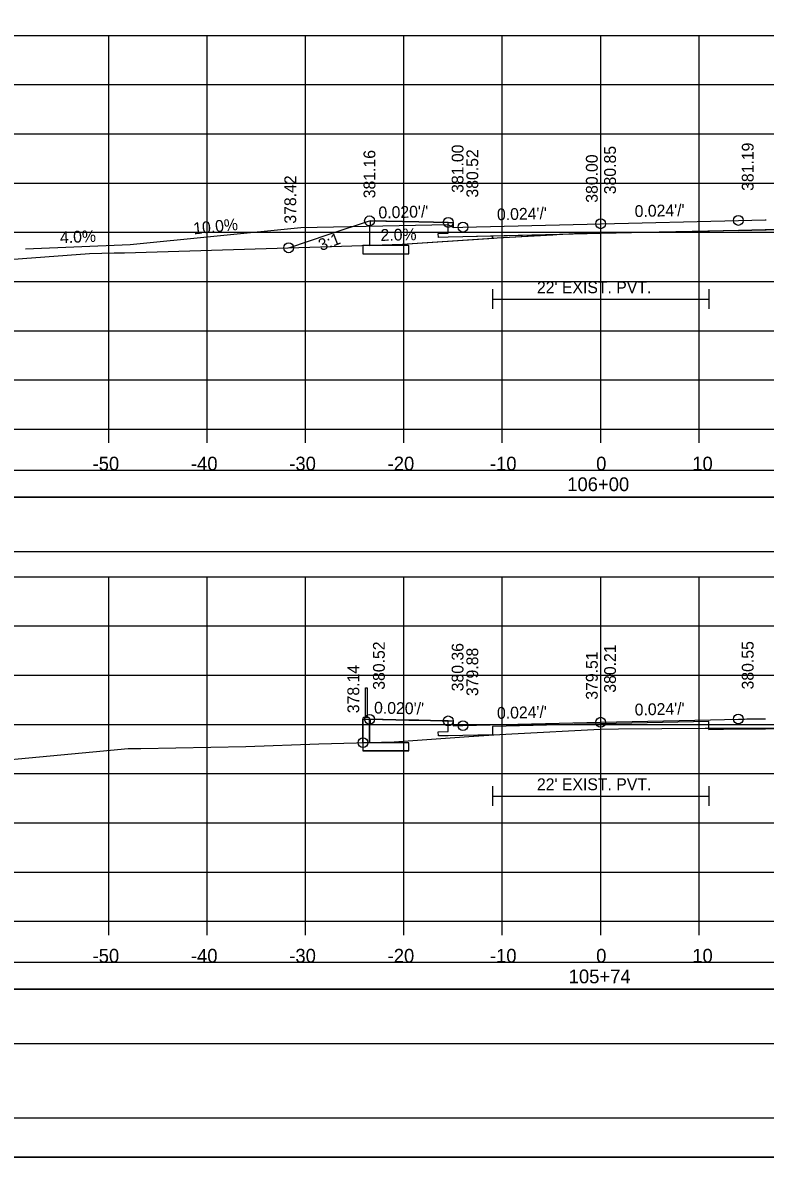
# Model space of a CAD drawing. Extents: x -37291014 to -37290680, y -936053 to -933067.
# Drawn here: x -37290901.9 to -37290826.4, y -934773.3 to -934658 of the extents above; entities that cross this region are included whole.
import ezdxf

# ---------------------------------------------------------------- set-up
doc = ezdxf.new("R2010")
doc.units = 0
for name, color, linetype in [('Default', 7, 'Continuous'), ('R_Alt Surface', 7, 'Continuous'), ('R_Axis', 7, 'Continuous'), ('R_Axis Annot', 7, 'Continuous'), ('R_Border', 7, 'Continuous'), ('R_Contours', 7, 'Continuous'), ('R_Drive', 7, 'Continuous'), ('R_Exist Surface', 7, 'Continuous'), ('R_Fin Surface', 7, 'Continuous'), ('R_Grid', 7, 'Continuous'), ('R_No Plot', 7, 'Continuous'), ('R_Water', 7, 'Continuous'), ('R_Xsect Elev', 7, 'Continuous'), ('R_Xsect Slope', 7, 'Continuous')]:
    doc.layers.add(name, color=color, linetype=linetype)

msp = doc.modelspace()

# ---------------------------------------------------------------- linework, layer by layer
at = {"layer": 'Default'}
for p, q in [((-37290867.02, -934728.59), (-37290867.02, -934725.59)), ((-37290867.02, -934725.59), (-37290866.85, -934725.59)), ((-37290866.85, -934725.59), (-37290866.85, -934728.59)), ((-37290867.21, -934728.61), (-37290867.27, -934728.67)), ((-37290866.67, -934728.59), (-37290867.21, -934728.59)), ((-37290867.21, -934728.59), (-37290867.21, -934728.61)), ((-37290866.67, -934728.61), (-37290867.21, -934728.61)), ((-37290866.67, -934728.61), (-37290866.67, -934728.59)), ((-37290866.6, -934728.67), (-37290866.67, -934728.61)), ((-37290867.27, -934728.67), (-37290867.27, -934731.99)), ((-37290866.6, -934731.16), (-37290866.6, -934728.67)), ((-37290862.6, -934731.99), (-37290867.27, -934731.99)), ((-37290862.6, -934731.16), (-37290866.6, -934731.16)), ((-37290862.6, -934731.99), (-37290862.6, -934731.16))]:
    msp.add_line(p, q, dxfattribs=at)
for points in [[(-37290992.31, -934706.2), (-37290693.89, -934706.2), (-37290693.89, -934703.5), (-37290992.31, -934703.5)], [(-37290992.31, -934711.72), (-37290693.89, -934711.72), (-37290693.89, -934706.2), (-37290992.31, -934706.2)], [(-37290992.31, -934756.2), (-37290693.89, -934756.2), (-37290693.89, -934753.5), (-37290992.31, -934753.5)], [(-37290992.31, -934761.72), (-37290693.89, -934761.72), (-37290693.89, -934756.2), (-37290992.31, -934756.2)]]:
    msp.add_lwpolyline(points, close=True, dxfattribs=at)
msp.add_lwpolyline([(-37290866.52, -934729.28), (-37290866.6, -934729.28), (-37290866.6, -934728.78), (-37290866.52, -934728.78), (-37290866.52, -934729.28)], dxfattribs=at)
at = {"layer": 'R_Alt Surface'}
for points in [[(-37290829.1, -934679.11), (-37290843.1, -934679.44), (-37290857.1, -934679.78), (-37290858.6, -934679.81), (-37290859.6, -934679.83), (-37290859.61, -934679.41), (-37290858.6, -934679.39), (-37290858.6, -934678.3)], [(-37290829.1, -934679.11), (-37290826.39, -934679.04), (-37290826.37, -934679.04), (-37290826.28, -934679.04)], [(-37290854.1, -934685.09), (-37290854.1, -934687.09)], [(-37290832.1, -934685.09), (-37290832.1, -934687.09)], [(-37290854.1, -934686.09), (-37290832.1, -934686.09)], [(-37290829.1, -934729.75), (-37290832.1, -934729.82), (-37290832.1, -934728.99), (-37290843.1, -934729.25), (-37290854.1, -934729.52), (-37290854.1, -934730.35), (-37290857.1, -934730.42), (-37290858.6, -934730.45), (-37290859.6, -934730.47), (-37290859.61, -934730.05), (-37290858.6, -934730.03), (-37290858.6, -934728.94)], [(-37290829.1, -934729.75), (-37290828.77, -934729.75), (-37290828.48, -934729.75), (-37290828.48, -934729.75), (-37290828.25, -934729.74), (-37290828.13, -934729.74), (-37290828.1, -934729.74), (-37290827.75, -934729.74), (-37290827.69, -934729.74), (-37290827.55, -934729.74), (-37290827.32, -934729.74), (-37290827.09, -934729.74), (-37290826.86, -934729.74), (-37290826.57, -934729.74), (-37290826.46, -934729.74), (-37290826.35, -934729.74)], [(-37290854.1, -934735.58), (-37290854.1, -934737.58)], [(-37290854.1, -934736.58), (-37290832.1, -934736.58)], [(-37290832.1, -934735.58), (-37290832.1, -934737.58)]]:
    msp.add_lwpolyline(points, dxfattribs=at)
at = {"layer": 'R_Axis'}
for p, q in [((-37290993.1, -934699.3), (-37290693.1, -934699.3)), ((-37290893.1, -934700.7), (-37290893.1, -934699.3)), ((-37290883.1, -934700.7), (-37290883.1, -934699.3)), ((-37290873.1, -934700.7), (-37290873.1, -934699.3)), ((-37290863.1, -934700.7), (-37290863.1, -934699.3)), ((-37290853.1, -934700.7), (-37290853.1, -934699.3)), ((-37290843.1, -934700.7), (-37290843.1, -934699.3)), ((-37290833.1, -934700.7), (-37290833.1, -934699.3)), ((-37290993.1, -934749.3), (-37290693.1, -934749.3)), ((-37290893.1, -934750.7), (-37290893.1, -934749.3)), ((-37290883.1, -934750.7), (-37290883.1, -934749.3)), ((-37290873.1, -934750.7), (-37290873.1, -934749.3)), ((-37290863.1, -934750.7), (-37290863.1, -934749.3)), ((-37290853.1, -934750.7), (-37290853.1, -934749.3)), ((-37290843.1, -934750.7), (-37290843.1, -934749.3)), ((-37290833.1, -934750.7), (-37290833.1, -934749.3))]:
    msp.add_line(p, q, dxfattribs=at)
at = {"layer": 'R_Border'}
msp.add_line((-37290684.92, -934769.3), (-37291001.1, -934769.3), dxfattribs=at)
at = {"layer": 'R_Contours'}
for p, q in [((-37290866.6, -934678.64), (-37290866.6, -934680.63)), ((-37290847.95, -934679.56), (-37290854.1, -934679.7)), ((-37290854.1, -934679.7), (-37290854.1, -934679.91)), ((-37290854.1, -934679.91), (-37290854.1, -934679.7)), ((-37290832.1, -934679.18), (-37290837.14, -934679.3)), ((-37290829.1, -934679.11), (-37290832.1, -934679.18)), ((-37290832.1, -934679.3), (-37290832.1, -934679.18)), ((-37290832.1, -934679.18), (-37290832.1, -934679.3)), ((-37290866.6, -934680.63), (-37290867.27, -934680.65)), ((-37290866.6, -934680.65), (-37290866.6, -934680.63)), ((-37290862.6, -934680.65), (-37290866.6, -934680.65)), ((-37290862.6, -934681.48), (-37290862.6, -934680.65)), ((-37290867.27, -934681.48), (-37290862.6, -934681.48)), ((-37290866.52, -934729.28), (-37290866.6, -934729.28)), ((-37290866.6, -934729.28), (-37290866.6, -934731.14)), ((-37290866.52, -934728.78), (-37290866.52, -934729.28)), ((-37290832.1, -934729.69), (-37290832.1, -934728.99)), ((-37290832.1, -934729.69), (-37290832.1, -934729.82)), ((-37290832.1, -934729.82), (-37290829.1, -934729.75)), ((-37290854.1, -934730.35), (-37290854.1, -934730.36)), ((-37290854.1, -934730.35), (-37290854.1, -934730.36)), ((-37290854.1, -934730.36), (-37290854.1, -934730.35)), ((-37290866.6, -934731.14), (-37290867.27, -934731.16)), ((-37290867.27, -934731.99), (-37290862.6, -934731.99)), ((-37290866.6, -934731.16), (-37290866.6, -934731.14)), ((-37290862.6, -934731.16), (-37290866.6, -934731.16)), ((-37290862.6, -934731.99), (-37290862.6, -934731.16))]:
    msp.add_line(p, q, dxfattribs=at)
for points in [[(-37290866.52, -934678.14), (-37290866.52, -934678.64), (-37290866.6, -934678.64)], [(-37290858.6, -934678.3), (-37290861.6, -934678.24), (-37290866.52, -934678.14)], [(-37290854.1, -934679.7), (-37290857.1, -934679.78), (-37290858.6, -934679.81), (-37290859.6, -934679.83), (-37290859.61, -934679.41), (-37290858.6, -934679.39), (-37290858.6, -934678.3)], [(-37290825.19, -934679.06), (-37290825.21, -934679.06), (-37290825.26, -934679.05), (-37290825.6, -934679.05), (-37290825.66, -934679.05), (-37290825.96, -934679.05), (-37290826.03, -934679.05), (-37290826.08, -934679.04), (-37290826.28, -934679.04), (-37290826.37, -934679.04), (-37290826.39, -934679.04), (-37290829.1, -934679.11)], [(-37290866.6, -934680.63), (-37290864.31, -934680.56), (-37290863.8, -934680.54), (-37290854.1, -934679.91)], [(-37290854.1, -934679.91), (-37290853.98, -934679.9), (-37290853.96, -934679.9), (-37290853.64, -934679.88), (-37290847.95, -934679.56)], [(-37290837.14, -934679.3), (-37290832.57, -934679.29), (-37290832.1, -934679.3)], [(-37290832.1, -934679.3), (-37290831.45, -934679.3), (-37290825.39, -934679.27), (-37290825.19, -934679.06)], [(-37290867.27, -934680.65), (-37290867.27, -934680.65), (-37290867.27, -934681.48)], [(-37290753.75, -934728.43), (-37290770.72, -934728.73), (-37290772.54, -934728.76), (-37290775.38, -934728.83), (-37290789.94, -934729.06), (-37290793.65, -934729.12), (-37290793.67, -934729.12), (-37290793.68, -934729.11), (-37290797.08, -934728.97), (-37290798.41, -934728.92), (-37290804.83, -934729.02), (-37290807.06, -934729.06), (-37290807.67, -934729.06), (-37290808.61, -934729.08), (-37290820.57, -934729.25), (-37290823.27, -934729.29), (-37290823.6, -934729.29), (-37290823.67, -934729.29), (-37290824.01, -934729.61), (-37290824.09, -934729.7), (-37290826.59, -934729.7), (-37290832.1, -934729.69)], [(-37290866.52, -934728.78), (-37290866.52, -934729.28), (-37290866.6, -934729.28), (-37290866.6, -934731.14)], [(-37290858.6, -934728.94), (-37290859.21, -934728.93), (-37290861.6, -934728.88), (-37290862.61, -934728.86), (-37290866.52, -934728.78)], [(-37290854.1, -934730.35), (-37290857.1, -934730.42), (-37290858.6, -934730.45), (-37290859.6, -934730.47), (-37290859.61, -934730.05), (-37290858.6, -934730.03), (-37290858.6, -934728.94)], [(-37290832.1, -934728.99), (-37290843.1, -934729.25), (-37290854.1, -934729.52), (-37290854.1, -934730.35)], [(-37290854.1, -934730.36), (-37290853.96, -934730.35), (-37290852.13, -934730.26), (-37290843.15, -934729.79), (-37290841.28, -934729.76), (-37290832.47, -934729.69), (-37290832.1, -934729.69)], [(-37290829.1, -934729.75), (-37290828.77, -934729.75), (-37290828.48, -934729.75), (-37290828.25, -934729.74), (-37290828.13, -934729.74), (-37290828.1, -934729.74), (-37290827.75, -934729.74), (-37290827.69, -934729.74), (-37290827.55, -934729.74), (-37290827.32, -934729.74), (-37290827.09, -934729.74), (-37290826.86, -934729.74), (-37290826.57, -934729.74), (-37290826.46, -934729.74), (-37290826.35, -934729.74)], [(-37290866.6, -934731.14), (-37290864.1, -934731.07), (-37290856.49, -934730.53), (-37290854.1, -934730.36)], [(-37290867.27, -934731.16), (-37290867.27, -934731.16), (-37290867.27, -934731.99)]]:
    msp.add_lwpolyline(points, dxfattribs=at)
at = {"layer": 'R_Drive'}
for p, q in [((-37290873.6, -934678.85), (-37290890.95, -934680.58)), ((-37290858.6, -934678.55), (-37290873.6, -934678.85)), ((-37290858.1, -934678.8), (-37290858.6, -934678.55)), ((-37290890.95, -934680.58), (-37290901.57, -934681.01))]:
    msp.add_line(p, q, dxfattribs=at)
at = {"layer": 'R_Exist Surface'}
for points in [[(-37290915.53, -934682.99), (-37290895.07, -934681.47), (-37290892.58, -934681.4), (-37290891.53, -934681.39), (-37290870.46, -934680.74), (-37290864.31, -934680.56), (-37290863.8, -934680.54), (-37290853.98, -934679.9), (-37290853.96, -934679.9), (-37290853.64, -934679.88), (-37290843.32, -934679.29), (-37290842.53, -934679.3), (-37290832.57, -934679.29), (-37290831.45, -934679.3), (-37290825.39, -934679.27)], [(-37290910.65, -934733.59), (-37290894.72, -934732.07), (-37290891.15, -934731.76), (-37290889.86, -934731.75), (-37290879.18, -934731.53), (-37290871.74, -934731.28), (-37290864.1, -934731.07), (-37290856.49, -934730.53), (-37290853.96, -934730.35), (-37290852.13, -934730.26), (-37290843.15, -934729.79), (-37290841.28, -934729.76), (-37290832.47, -934729.69), (-37290826.59, -934729.7), (-37290824.09, -934729.7)]]:
    msp.add_lwpolyline(points, dxfattribs=at)
at = {"layer": 'R_Fin Surface'}
for points in [[(-37290874.82, -934680.88), (-37290870.71, -934679.51), (-37290866.6, -934678.14), (-37290861.6, -934678.24), (-37290858.6, -934678.3), (-37290858.1, -934678.3), (-37290858.1, -934678.8), (-37290857.1, -934678.78), (-37290843.1, -934678.44), (-37290829.1, -934678.1)], [(-37290829.1, -934678.1), (-37290826.39, -934678.04), (-37290826.37, -934678.04), (-37290826.28, -934678.04)], [(-37290867.27, -934731.16), (-37290867.27, -934729.25), (-37290867.27, -934728.78), (-37290867.14, -934728.78), (-37290866.6, -934728.78), (-37290862.61, -934728.86), (-37290861.6, -934728.88), (-37290859.21, -934728.93), (-37290858.6, -934728.94), (-37290858.5, -934728.94), (-37290858.1, -934728.94), (-37290858.1, -934729.34), (-37290858.1, -934729.44), (-37290857.3, -934729.42), (-37290857.1, -934729.42), (-37290845.94, -934729.15), (-37290843.1, -934729.08), (-37290831.94, -934728.82), (-37290829.1, -934728.75)], [(-37290829.1, -934728.75), (-37290828.77, -934728.75), (-37290828.48, -934728.75), (-37290828.48, -934728.75), (-37290828.25, -934728.74), (-37290828.14, -934728.74), (-37290828.1, -934728.74), (-37290827.75, -934728.74), (-37290827.69, -934728.74), (-37290827.55, -934728.74), (-37290827.32, -934728.74), (-37290827.09, -934728.74), (-37290826.86, -934728.74), (-37290826.58, -934728.74), (-37290826.46, -934728.74), (-37290826.35, -934728.74)]]:
    msp.add_lwpolyline(points, dxfattribs=at)
at = {"layer": 'R_Grid'}
for p, q in [((-37290993.1, -934659.3), (-37290693.1, -934659.3)), ((-37290893.1, -934699.3), (-37290893.1, -934659.3)), ((-37290883.1, -934699.3), (-37290883.1, -934659.3)), ((-37290873.1, -934699.3), (-37290873.1, -934659.3)), ((-37290863.1, -934699.3), (-37290863.1, -934659.3)), ((-37290853.1, -934699.3), (-37290853.1, -934659.3)), ((-37290843.1, -934699.3), (-37290843.1, -934659.3)), ((-37290833.1, -934699.3), (-37290833.1, -934659.3)), ((-37290993.1, -934664.3), (-37290693.1, -934664.3)), ((-37290993.1, -934669.3), (-37290693.1, -934669.3)), ((-37290993.1, -934674.3), (-37290693.1, -934674.3)), ((-37290993.1, -934679.3), (-37290693.1, -934679.3)), ((-37290993.1, -934684.3), (-37290693.1, -934684.3)), ((-37290993.1, -934689.3), (-37290693.1, -934689.3)), ((-37290993.1, -934694.3), (-37290693.1, -934694.3)), ((-37290993.1, -934699.3), (-37290693.1, -934699.3)), ((-37290993.1, -934714.3), (-37290693.1, -934714.3)), ((-37290893.1, -934749.3), (-37290893.1, -934714.3)), ((-37290883.1, -934749.3), (-37290883.1, -934714.3)), ((-37290873.1, -934749.3), (-37290873.1, -934714.3)), ((-37290863.1, -934749.3), (-37290863.1, -934714.3)), ((-37290853.1, -934749.3), (-37290853.1, -934714.3)), ((-37290843.1, -934749.3), (-37290843.1, -934714.3)), ((-37290833.1, -934749.3), (-37290833.1, -934714.3)), ((-37290993.1, -934719.3), (-37290693.1, -934719.3)), ((-37290993.1, -934724.3), (-37290693.1, -934724.3)), ((-37290993.1, -934729.3), (-37290693.1, -934729.3)), ((-37290993.1, -934734.3), (-37290693.1, -934734.3)), ((-37290993.1, -934739.3), (-37290693.1, -934739.3)), ((-37290993.1, -934744.3), (-37290693.1, -934744.3)), ((-37290993.1, -934749.3), (-37290693.1, -934749.3))]:
    msp.add_line(p, q, dxfattribs=at)
at = {"layer": 'R_No Plot'}
msp.add_line((-37291013.5, -934773.27), (-37290680.17, -934773.27), dxfattribs=at)
for points in [[(-37291013.51, -934559.94), (-37290680.17, -934559.94), (-37290680.17, -934773.28), (-37291013.51, -934773.28)], [(-37290767.18, -934563.84), (-37290747.56, -934563.84), (-37290747.56, -934573.72), (-37290731.45, -934573.72), (-37290708.25, -934573.72), (-37290708.25, -934598.05), (-37290684.92, -934598.05), (-37290684.92, -934769.3), (-37291001.1, -934769.3), (-37291001.1, -934563.84)]]:
    msp.add_lwpolyline(points, close=True, dxfattribs=at)
for centre in [(-37290866.6, -934678.14), (-37290858.6, -934678.3), (-37290829.1, -934678.1), (-37290829.1, -934678.1), (-37290857.1, -934678.78), (-37290843.1, -934678.44), (-37290874.82, -934680.88), (-37290866.6, -934728.78), (-37290858.6, -934728.94), (-37290843.1, -934729.08), (-37290829.1, -934728.75), (-37290829.1, -934728.75), (-37290857.1, -934729.42), (-37290867.27, -934731.16)]:
    msp.add_circle(centre, 0.5, dxfattribs=at)
at = {"layer": 'R_Xsect Elev'}
for p, q in [((-37290843.1, -934679.3), (-37290843.1, -934669.3)), ((-37290843.1, -934729.79), (-37290843.1, -934719.79))]:
    msp.add_line(p, q, dxfattribs=at)

# ---------------------------------------------------------------- texts
at = {"layer": 'R_Axis Annot'}
for s, p in [('-50', (-37290894.76, -934703.5)), ('-40', (-37290884.76, -934703.5)), ('-30', (-37290874.76, -934703.5)), ('-20', (-37290864.76, -934703.5)), ('-10', (-37290854.36, -934703.5)), ('0', (-37290843.56, -934703.5)), ('10', (-37290833.79, -934703.5)), ('106+00', (-37290846.5, -934705.6)), ('-50', (-37290894.76, -934753.5)), ('-40', (-37290884.76, -934753.5)), ('-30', (-37290874.76, -934753.5)), ('-20', (-37290864.76, -934753.5)), ('-10', (-37290854.36, -934753.5)), ('0', (-37290843.56, -934753.5)), ('10', (-37290833.79, -934753.5)), ('105+74', (-37290846.35, -934755.6))]:
    msp.add_text(s, height=1.4, dxfattribs=at).set_placement(p)
at = {"layer": 'R_Water'}
for p in [(-37290849.58, -934685.49), (-37290849.58, -934735.98)]:
    msp.add_text("22' EXIST. PVT.", height=1.2, dxfattribs=at).set_placement(p)
at = {"layer": 'R_Xsect Elev'}
for s, rotation, p in [('381.00', 90, (-37290857.05, -934675.3)), ('380.52', 90, (-37290855.55, -934675.78)), ('380.85', 90, (-37290841.55, -934675.44)), ('381.19', 90, (-37290827.55, -934675.1)), ('381.16', 90, (-37290866.01, -934675.85)), ('380.00', 90, (-37290843.4, -934676.3)), ('378.42', 90, (-37290874.06, -934678.43)), ('10.0%', 5.7106, (-37290884.46, -934679.52)), ('2.0%', 1.1458, (-37290865.47, -934680.18)), ('4.0%', 2.2906, (-37290898.05, -934680.42)), ('380.52', 90, (-37290865.05, -934725.78)), ('380.36', 90, (-37290857.05, -934725.94)), ('379.88', 90, (-37290855.55, -934726.42)), ('380.21', 90, (-37290841.55, -934726.08)), ('380.55', 90, (-37290827.55, -934725.75)), ('379.51', 90, (-37290843.4, -934726.79)), ('378.14', 90, (-37290867.65, -934728.16))]:
    msp.add_text(s, height=1.2, rotation=rotation, dxfattribs=at).set_placement(p)
at = {"layer": 'R_Xsect Slope'}
for s, rotation, p in [("0.020'/'", 1.3748, (-37290865.68, -934677.9)), ("0.024'/'", 1.3748, (-37290853.63, -934678.09)), ("0.024'/'", 1.3748, (-37290839.63, -934677.76)), ('3:1', 20.7828, (-37290871.53, -934681.22)), ("0.020'/'", 358.8542, (-37290866.15, -934728.19)), ("0.024'/'", 1.3748, (-37290853.63, -934728.74)), ("0.024'/'", 1.3748, (-37290839.63, -934728.4))]:
    msp.add_text(s, height=1.2, rotation=rotation, dxfattribs=at).set_placement(p)

doc.saveas('drawing.dxf')
